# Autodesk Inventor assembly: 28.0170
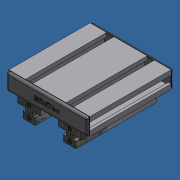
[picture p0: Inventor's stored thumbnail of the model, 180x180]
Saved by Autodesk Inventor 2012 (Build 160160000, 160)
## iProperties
Created: 2007-06
Part Number: 28.0170
Document SubType Name: Assembly
Designer: Andy Moles
Description: SLIDE LWN-S
Vendor: S
Author: Andy Moles
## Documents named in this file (4)
- C:\Andys Backup Data\ANDY'S INVENTOR\INVENTOR LIBRARIES\PARTS LIBRARY\READY FOR USE MODULES LG\28.0170 SLIDE LWN-S.iam
- C:\Andys Backup Data\ANDY'S INVENTOR\INVENTOR LIBRARIES\PARTS LIBRARY\READY FOR USE MODULES LG\SUBCOMPONENTS\28.0237 SLIDE LWN-S 90X19.ipt
- C:\Andys Backup Data\ANDY'S INVENTOR\INVENTOR LIBRARIES\PARTS LIBRARY\COMPONENTS LG\22.1096 SLIDE RAIL LN-S.iam
- C:\Andys Backup Data\ANDY'S INVENTOR\INVENTOR LIBRARIES\PARTS LIBRARY\END CAPS\22.1014_1 END CAP 90X19 GRAY.ipt
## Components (5 placed, 3 different names)
1. 28.0237 SLIDE LWN-S 90X19:1 — Insert:1, Angle:1, Mate:1, Insert:2, Angle:2, Mate:5, Mate:6, Mate:7, Flush:1, Flush:2, Mate:8, Flush:3, Flush:4
2. 22.1096 SLIDE RAIL LN-S:1 [sub-assembly] — Insert:1, Angle:1, Mate:4
3. 22.1096 SLIDE RAIL LN-S:2 [sub-assembly] — Mate:1, Insert:2, Angle:2
4. 22.1014_1 END CAP 90X19 GRAY:1 — Mate:7, Flush:1, Flush:2
5. 22.1014_1 END CAP 90X19 GRAY:2 — Mate:8, Flush:3, Flush:4
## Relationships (14: Mate 6, Flush 4, Insert 2, Angle 2)
- Insert:1: 28.0237 SLIDE LWN-S 90X19:1 ↔ 22.1096 SLIDE RAIL LN-S:1
- Angle:1: 28.0237 SLIDE LWN-S 90X19:1 ↔ 22.1096 SLIDE RAIL LN-S:1
- Mate:1: 28.0237 SLIDE LWN-S 90X19:1 ↔ 22.1096 SLIDE RAIL LN-S:2
- Insert:2: 28.0237 SLIDE LWN-S 90X19:1 ↔ 22.1096 SLIDE RAIL LN-S:2
- Angle:2: 28.0237 SLIDE LWN-S 90X19:1 ↔ 22.1096 SLIDE RAIL LN-S:2
- Mate:4: 22.1096 SLIDE RAIL LN-S:1
- Mate:5: 28.0237 SLIDE LWN-S 90X19:1
- Mate:6: 28.0237 SLIDE LWN-S 90X19:1
- Mate:7: 28.0237 SLIDE LWN-S 90X19:1 ↔ 22.1014_1 END CAP 90X19 GRAY:1
- Flush:1: 28.0237 SLIDE LWN-S 90X19:1 ↔ 22.1014_1 END CAP 90X19 GRAY:1
- Flush:2: 28.0237 SLIDE LWN-S 90X19:1 ↔ 22.1014_1 END CAP 90X19 GRAY:1
- Mate:8: 28.0237 SLIDE LWN-S 90X19:1 ↔ 22.1014_1 END CAP 90X19 GRAY:2
- Flush:3: 28.0237 SLIDE LWN-S 90X19:1 ↔ 22.1014_1 END CAP 90X19 GRAY:2
- Flush:4: 28.0237 SLIDE LWN-S 90X19:1 ↔ 22.1014_1 END CAP 90X19 GRAY:2
